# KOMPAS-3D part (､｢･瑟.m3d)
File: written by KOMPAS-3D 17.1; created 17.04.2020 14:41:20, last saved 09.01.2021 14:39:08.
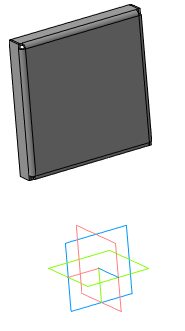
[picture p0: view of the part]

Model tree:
1. Эскиз:1
2. Листовое тело:1
     Расстояние 1 = 10; Радиус сгиба = 5
3. Сгиб:1
     Радиус сгиба = 2; Коэффициент = 0.4; Величина сгиба = 10; Радиус сгиба = 2; Коэффициент = 0.4; Величина сгиба = 10; Радиус сгиба = 2; Толщина листового тела = 1.5; Ширина освобождения сгиба = 3; Ширина сгиба = 100; Длина 2 = 10
4. Сгиб:2
     Радиус сгиба = 2; Коэффициент = 0.4; Величина сгиба = 10; Радиус сгиба = 2; Коэффициент = 0.4; Величина сгиба = 10; Радиус сгиба = 2; Толщина листового тела = 1.5; Ширина освобождения сгиба = 3; Ширина сгиба = 93; Длина 1 = 2; Длина 2 = 2; Длина 2 = 10

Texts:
  ex71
